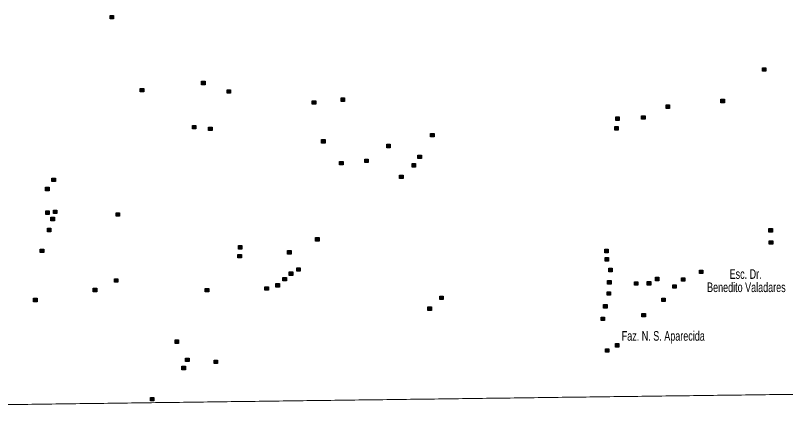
# Model space of a CAD drawing. Extents: x 265.7 to 292.1, y 7676.2 to 7704.2.
# Drawn here: x 279.53 to 285.94, y 7676.18 to 7679.6 of the extents above; entities that cross this region are included whole.
import ezdxf

# ---------------------------------------------------------------- set-up
doc = ezdxf.new("R2010")
doc.units = 0
doc.header["$LTSCALE"] = 0.032
doc.layers.add('2', color=7, linetype='Continuous', lineweight=25)
doc.layers.add('63', color=7, linetype='Continuous', lineweight=13)
doc.layers.add('61', color=7, linetype='Continuous')

msp = doc.modelspace()

# ---------------------------------------------------------------- hatches: boundary and pattern name
at = {"layer": '2'}
for points in [[(280.3175, 7679.5959), (280.3465, 7679.5959), (280.3465, 7679.5669), (280.3175, 7679.5669)], [(285.7441, 7679.1601), (285.7731, 7679.1601), (285.7731, 7679.1311), (285.7441, 7679.1311)], [(281.0785, 7679.0487), (281.1075, 7679.0487), (281.1075, 7679.0197), (281.0785, 7679.0197)], [(280.5692, 7678.9889), (280.5982, 7678.9889), (280.5982, 7678.9599), (280.5692, 7678.9599)], [(281.2916, 7678.9777), (281.3206, 7678.9777), (281.3206, 7678.9487), (281.2916, 7678.9487)], [(282.0001, 7678.8864), (282.0291, 7678.8864), (282.0291, 7678.8574), (282.0001, 7678.8574)], [(282.2391, 7678.9099), (282.2681, 7678.9099), (282.2681, 7678.8809), (282.2391, 7678.8809)], [(285.3995, 7678.8985), (285.4285, 7678.8985), (285.4285, 7678.8695), (285.3995, 7678.8695)], [(284.9427, 7678.8518), (284.9717, 7678.8518), (284.9717, 7678.8228), (284.9427, 7678.8228)], [(284.5247, 7678.7517), (284.5537, 7678.7517), (284.5537, 7678.7227), (284.5247, 7678.7227)], [(284.7393, 7678.7614), (284.7683, 7678.7614), (284.7683, 7678.7324), (284.7393, 7678.7324)], [(281.0027, 7678.6807), (281.0317, 7678.6807), (281.0317, 7678.6517), (281.0027, 7678.6517)], [(281.1367, 7678.6677), (281.1657, 7678.6677), (281.1657, 7678.6387), (281.1367, 7678.6387)], [(284.5158, 7678.671), (284.5448, 7678.671), (284.5448, 7678.642), (284.5158, 7678.642)], [(282.0776, 7678.5637), (282.1066, 7678.5637), (282.1066, 7678.5347), (282.0776, 7678.5347)], [(282.984, 7678.6145), (283.013, 7678.6145), (283.013, 7678.5855), (282.984, 7678.5855)], [(282.6201, 7678.5241), (282.6491, 7678.5241), (282.6491, 7678.4951), (282.6201, 7678.4951)], [(282.8791, 7678.4337), (282.9081, 7678.4337), (282.9081, 7678.4047), (282.8791, 7678.4047)], [(282.227, 7678.382), (282.256, 7678.382), (282.256, 7678.353), (282.227, 7678.353)], [(282.4367, 7678.4006), (282.4657, 7678.4006), (282.4657, 7678.3716), (282.4367, 7678.3716)], [(282.8299, 7678.3636), (282.8589, 7678.3636), (282.8589, 7678.3346), (282.8299, 7678.3346)], [(279.8341, 7678.2432), (279.8631, 7678.2432), (279.8631, 7678.2142), (279.8341, 7678.2142)], [(282.7258, 7678.2683), (282.7548, 7678.2683), (282.7548, 7678.2393), (282.7258, 7678.2393)], [(279.7816, 7678.1673), (279.8106, 7678.1673), (279.8106, 7678.1383), (279.7816, 7678.1383)], [(279.7824, 7677.9705), (279.8114, 7677.9705), (279.8114, 7677.9415), (279.7824, 7677.9415)], [(279.8252, 7677.9171), (279.8542, 7677.9171), (279.8542, 7677.8881), (279.8252, 7677.8881)], [(279.8462, 7677.9769), (279.8752, 7677.9769), (279.8752, 7677.9479), (279.8462, 7677.9479)], [(280.3676, 7677.9552), (280.3966, 7677.9552), (280.3966, 7677.9262), (280.3676, 7677.9262)], [(279.7962, 7677.8261), (279.8252, 7677.8261), (279.8252, 7677.7971), (279.7962, 7677.7971)], [(285.7982, 7677.8236), (285.8272, 7677.8236), (285.8272, 7677.7946), (285.7982, 7677.7946)], [(282.0276, 7677.7477), (282.0566, 7677.7477), (282.0566, 7677.7187), (282.0276, 7677.7187)], [(285.8014, 7677.7219), (285.8304, 7677.7219), (285.8304, 7677.6929), (285.8014, 7677.6929)], [(281.386, 7677.6815), (281.415, 7677.6815), (281.415, 7677.6525), (281.386, 7677.6525)], [(279.7373, 7677.6525), (279.7663, 7677.6525), (279.7663, 7677.6235), (279.7373, 7677.6235)], [(281.3811, 7677.6088), (281.4101, 7677.6088), (281.4101, 7677.5798), (281.3811, 7677.5798)], [(281.7945, 7677.6396), (281.8235, 7677.6396), (281.8235, 7677.6106), (281.7945, 7677.6106)], [(284.4326, 7677.6518), (284.4616, 7677.6518), (284.4616, 7677.6228), (284.4326, 7677.6228)], [(284.4359, 7677.5815), (284.4649, 7677.5815), (284.4649, 7677.5525), (284.4359, 7677.5525)], [(281.8702, 7677.4976), (281.8992, 7677.4976), (281.8992, 7677.4686), (281.8702, 7677.4686)], [(284.4658, 7677.4927), (284.4948, 7677.4927), (284.4948, 7677.4637), (284.4658, 7677.4637)], [(285.2203, 7677.4782), (285.2493, 7677.4782), (285.2493, 7677.4492), (285.2203, 7677.4492)], [(280.3547, 7677.4063), (280.3837, 7677.4063), (280.3837, 7677.3773), (280.3547, 7677.3773)], [(281.7562, 7677.4163), (281.7852, 7677.4163), (281.7852, 7677.3873), (281.7562, 7677.3873)], [(281.8082, 7677.4629), (281.8372, 7677.4629), (281.8372, 7677.4339), (281.8082, 7677.4339)], [(284.8548, 7677.4184), (284.8838, 7677.4184), (284.8838, 7677.3894), (284.8548, 7677.3894)], [(285.071, 7677.4136), (285.1, 7677.4136), (285.1, 7677.3846), (285.071, 7677.3846)], [(281.6056, 7677.3386), (281.6346, 7677.3386), (281.6346, 7677.3096), (281.6056, 7677.3096)], [(281.6968, 7677.3652), (281.7258, 7677.3652), (281.7258, 7677.3362), (281.6968, 7677.3362)], [(284.456, 7677.3909), (284.485, 7677.3909), (284.485, 7677.3619), (284.456, 7677.3619)], [(284.6804, 7677.3812), (284.7094, 7677.3812), (284.7094, 7677.3522), (284.6804, 7677.3522)], [(284.7868, 7677.3829), (284.8158, 7677.3829), (284.8158, 7677.3539), (284.7868, 7677.3539)], [(284.9992, 7677.3555), (285.0282, 7677.3555), (285.0282, 7677.3265), (284.9992, 7677.3265)], [(280.1779, 7677.3264), (280.2069, 7677.3264), (280.2069, 7677.2974), (280.1779, 7677.2974)], [(281.1093, 7677.3256), (281.1383, 7677.3256), (281.1383, 7677.2966), (281.1093, 7677.2966)], [(284.452, 7677.2973), (284.481, 7677.2973), (284.481, 7677.2683), (284.452, 7677.2683)], [(279.6816, 7677.2434), (279.7106, 7677.2434), (279.7106, 7677.2144), (279.6816, 7677.2144)], [(283.0607, 7677.2619), (283.0897, 7677.2619), (283.0897, 7677.2329), (283.0607, 7677.2329)], [(284.9064, 7677.2449), (284.9354, 7677.2449), (284.9354, 7677.2159), (284.9064, 7677.2159)], [(282.9615, 7677.1715), (282.9905, 7677.1715), (282.9905, 7677.1425), (282.9615, 7677.1425)], [(284.423, 7677.1908), (284.452, 7677.1908), (284.452, 7677.1618), (284.423, 7677.1618)], [(284.402, 7677.0867), (284.431, 7677.0867), (284.431, 7677.0577), (284.402, 7677.0577)], [(284.7425, 7677.1182), (284.7715, 7677.1182), (284.7715, 7677.0892), (284.7425, 7677.0892)], [(280.8581, 7676.8971), (280.8871, 7676.8971), (280.8871, 7676.8681), (280.8581, 7676.8681)], [(284.5223, 7676.8665), (284.5513, 7676.8665), (284.5513, 7676.8375), (284.5223, 7676.8375)], [(284.4384, 7676.8244), (284.4674, 7676.8244), (284.4674, 7676.7954), (284.4384, 7676.7954)], [(280.9454, 7676.7454), (280.9744, 7676.7454), (280.9744, 7676.7164), (280.9454, 7676.7164)], [(281.1834, 7676.7293), (281.2124, 7676.7293), (281.2124, 7676.7003), (281.1834, 7676.7003)], [(280.9155, 7676.6776), (280.9445, 7676.6776), (280.9445, 7676.6486), (280.9155, 7676.6486)], [(280.654, 7676.4186), (280.683, 7676.4186), (280.683, 7676.3896), (280.654, 7676.3896)]]:
    msp.add_hatch(color=256, dxfattribs=at).paths.add_polyline_path(points)

# ---------------------------------------------------------------- linework, layer by layer
for points in [[(280.3175, 7679.5959), (280.3465, 7679.5959), (280.3465, 7679.5669), (280.3175, 7679.5669)], [(285.7441, 7679.1601), (285.7731, 7679.1601), (285.7731, 7679.1311), (285.7441, 7679.1311)], [(281.0785, 7679.0487), (281.1075, 7679.0487), (281.1075, 7679.0197), (281.0785, 7679.0197)], [(280.5692, 7678.9889), (280.5982, 7678.9889), (280.5982, 7678.9599), (280.5692, 7678.9599)], [(281.2916, 7678.9777), (281.3206, 7678.9777), (281.3206, 7678.9487), (281.2916, 7678.9487)], [(282.0001, 7678.8864), (282.0291, 7678.8864), (282.0291, 7678.8574), (282.0001, 7678.8574)], [(282.2391, 7678.9099), (282.2681, 7678.9099), (282.2681, 7678.8809), (282.2391, 7678.8809)], [(285.3995, 7678.8985), (285.4285, 7678.8985), (285.4285, 7678.8695), (285.3995, 7678.8695)], [(284.9427, 7678.8518), (284.9717, 7678.8518), (284.9717, 7678.8228), (284.9427, 7678.8228)], [(284.5247, 7678.7517), (284.5537, 7678.7517), (284.5537, 7678.7227), (284.5247, 7678.7227)], [(284.7393, 7678.7614), (284.7683, 7678.7614), (284.7683, 7678.7324), (284.7393, 7678.7324)], [(281.0027, 7678.6807), (281.0317, 7678.6807), (281.0317, 7678.6517), (281.0027, 7678.6517)], [(281.1367, 7678.6677), (281.1657, 7678.6677), (281.1657, 7678.6387), (281.1367, 7678.6387)], [(284.5158, 7678.671), (284.5448, 7678.671), (284.5448, 7678.642), (284.5158, 7678.642)], [(282.0776, 7678.5637), (282.1066, 7678.5637), (282.1066, 7678.5347), (282.0776, 7678.5347)], [(282.984, 7678.6145), (283.013, 7678.6145), (283.013, 7678.5855), (282.984, 7678.5855)], [(282.6201, 7678.5241), (282.6491, 7678.5241), (282.6491, 7678.4951), (282.6201, 7678.4951)], [(282.8791, 7678.4337), (282.9081, 7678.4337), (282.9081, 7678.4047), (282.8791, 7678.4047)], [(282.227, 7678.382), (282.256, 7678.382), (282.256, 7678.353), (282.227, 7678.353)], [(282.4367, 7678.4006), (282.4657, 7678.4006), (282.4657, 7678.3716), (282.4367, 7678.3716)], [(282.8299, 7678.3636), (282.8589, 7678.3636), (282.8589, 7678.3346), (282.8299, 7678.3346)], [(279.8341, 7678.2432), (279.8631, 7678.2432), (279.8631, 7678.2142), (279.8341, 7678.2142)], [(282.7258, 7678.2683), (282.7548, 7678.2683), (282.7548, 7678.2393), (282.7258, 7678.2393)], [(279.7816, 7678.1673), (279.8106, 7678.1673), (279.8106, 7678.1383), (279.7816, 7678.1383)], [(279.7824, 7677.9705), (279.8114, 7677.9705), (279.8114, 7677.9415), (279.7824, 7677.9415)], [(279.8252, 7677.9171), (279.8542, 7677.9171), (279.8542, 7677.8881), (279.8252, 7677.8881)], [(279.8462, 7677.9769), (279.8752, 7677.9769), (279.8752, 7677.9479), (279.8462, 7677.9479)], [(280.3676, 7677.9552), (280.3966, 7677.9552), (280.3966, 7677.9262), (280.3676, 7677.9262)], [(279.7962, 7677.8261), (279.8252, 7677.8261), (279.8252, 7677.7971), (279.7962, 7677.7971)], [(285.7982, 7677.8236), (285.8272, 7677.8236), (285.8272, 7677.7946), (285.7982, 7677.7946)], [(282.0276, 7677.7477), (282.0566, 7677.7477), (282.0566, 7677.7187), (282.0276, 7677.7187)], [(285.8014, 7677.7219), (285.8304, 7677.7219), (285.8304, 7677.6929), (285.8014, 7677.6929)], [(281.386, 7677.6815), (281.415, 7677.6815), (281.415, 7677.6525), (281.386, 7677.6525)], [(279.7373, 7677.6525), (279.7663, 7677.6525), (279.7663, 7677.6235), (279.7373, 7677.6235)], [(281.3811, 7677.6088), (281.4101, 7677.6088), (281.4101, 7677.5798), (281.3811, 7677.5798)], [(281.7945, 7677.6396), (281.8235, 7677.6396), (281.8235, 7677.6106), (281.7945, 7677.6106)], [(284.4326, 7677.6518), (284.4616, 7677.6518), (284.4616, 7677.6228), (284.4326, 7677.6228)], [(284.4359, 7677.5815), (284.4649, 7677.5815), (284.4649, 7677.5525), (284.4359, 7677.5525)], [(281.8702, 7677.4976), (281.8992, 7677.4976), (281.8992, 7677.4686), (281.8702, 7677.4686)], [(284.4658, 7677.4927), (284.4948, 7677.4927), (284.4948, 7677.4637), (284.4658, 7677.4637)], [(285.2203, 7677.4782), (285.2493, 7677.4782), (285.2493, 7677.4492), (285.2203, 7677.4492)], [(280.3547, 7677.4063), (280.3837, 7677.4063), (280.3837, 7677.3773), (280.3547, 7677.3773)], [(281.7562, 7677.4163), (281.7852, 7677.4163), (281.7852, 7677.3873), (281.7562, 7677.3873)], [(281.8082, 7677.4629), (281.8372, 7677.4629), (281.8372, 7677.4339), (281.8082, 7677.4339)], [(284.8548, 7677.4184), (284.8838, 7677.4184), (284.8838, 7677.3894), (284.8548, 7677.3894)], [(285.071, 7677.4136), (285.1, 7677.4136), (285.1, 7677.3846), (285.071, 7677.3846)], [(281.6056, 7677.3386), (281.6346, 7677.3386), (281.6346, 7677.3096), (281.6056, 7677.3096)], [(281.6968, 7677.3652), (281.7258, 7677.3652), (281.7258, 7677.3362), (281.6968, 7677.3362)], [(284.456, 7677.3909), (284.485, 7677.3909), (284.485, 7677.3619), (284.456, 7677.3619)], [(284.6804, 7677.3812), (284.7094, 7677.3812), (284.7094, 7677.3522), (284.6804, 7677.3522)], [(284.7868, 7677.3829), (284.8158, 7677.3829), (284.8158, 7677.3539), (284.7868, 7677.3539)], [(284.9992, 7677.3555), (285.0282, 7677.3555), (285.0282, 7677.3265), (284.9992, 7677.3265)], [(280.1779, 7677.3264), (280.2069, 7677.3264), (280.2069, 7677.2974), (280.1779, 7677.2974)], [(281.1093, 7677.3256), (281.1383, 7677.3256), (281.1383, 7677.2966), (281.1093, 7677.2966)], [(284.452, 7677.2973), (284.481, 7677.2973), (284.481, 7677.2683), (284.452, 7677.2683)], [(279.6816, 7677.2434), (279.7106, 7677.2434), (279.7106, 7677.2144), (279.6816, 7677.2144)], [(283.0607, 7677.2619), (283.0897, 7677.2619), (283.0897, 7677.2329), (283.0607, 7677.2329)], [(284.9064, 7677.2449), (284.9354, 7677.2449), (284.9354, 7677.2159), (284.9064, 7677.2159)], [(282.9615, 7677.1715), (282.9905, 7677.1715), (282.9905, 7677.1425), (282.9615, 7677.1425)], [(284.423, 7677.1908), (284.452, 7677.1908), (284.452, 7677.1618), (284.423, 7677.1618)], [(284.402, 7677.0867), (284.431, 7677.0867), (284.431, 7677.0577), (284.402, 7677.0577)], [(284.7425, 7677.1182), (284.7715, 7677.1182), (284.7715, 7677.0892), (284.7425, 7677.0892)], [(280.8581, 7676.8971), (280.8871, 7676.8971), (280.8871, 7676.8681), (280.8581, 7676.8681)], [(284.5223, 7676.8665), (284.5513, 7676.8665), (284.5513, 7676.8375), (284.5223, 7676.8375)], [(284.4384, 7676.8244), (284.4674, 7676.8244), (284.4674, 7676.7954), (284.4384, 7676.7954)], [(280.9454, 7676.7454), (280.9744, 7676.7454), (280.9744, 7676.7164), (280.9454, 7676.7164)], [(281.1834, 7676.7293), (281.2124, 7676.7293), (281.2124, 7676.7003), (281.1834, 7676.7003)], [(280.9155, 7676.6776), (280.9445, 7676.6776), (280.9445, 7676.6486), (280.9155, 7676.6486)], [(280.654, 7676.4186), (280.683, 7676.4186), (280.683, 7676.3896), (280.654, 7676.3896)]]:
    msp.add_lwpolyline(points, close=True, dxfattribs=at)
at = {"layer": '63'}
msp.add_spline([(266.1055, 7676.1764), (266.6361, 7676.1838), (267.1667, 7676.1913), (267.6972, 7676.1987), (268.2278, 7676.2061), (268.7584, 7676.2135), (269.2889, 7676.2209), (269.8195, 7676.2283), (270.3501, 7676.2356), (270.8806, 7676.2429), (271.4112, 7676.2502), (271.9418, 7676.2575), (272.4723, 7676.2648), (273.0029, 7676.2721), (273.5335, 7676.2793), (274.064, 7676.2865), (274.5946, 7676.2937), (275.1251, 7676.3009), (275.6557, 7676.3081), (276.1862, 7676.3153), (276.7168, 7676.3224), (277.2473, 7676.3295), (277.7779, 7676.3366), (278.3084, 7676.3437), (278.839, 7676.3508), (279.3695, 7676.3578), (279.9, 7676.3649), (280.4306, 7676.3719), (280.9611, 7676.3789), (281.4917, 7676.3859), (282.0222, 7676.3929), (282.5527, 7676.3998), (283.0833, 7676.4067), (283.6138, 7676.4137), (284.1443, 7676.4206), (284.6749, 7676.4275), (285.2054, 7676.4343), (285.7359, 7676.4412), (286.2665, 7676.448), (286.797, 7676.4548), (287.3275, 7676.4616), (287.858, 7676.4684), (288.3886, 7676.4752), (288.9191, 7676.4819), (289.4496, 7676.4887), (289.9801, 7676.4954), (290.5106, 7676.5021), (291.0411, 7676.5087), (291.5717, 7676.5154), (292.1022, 7676.5221)], degree=3, dxfattribs=at)

# ---------------------------------------------------------------- texts
at = {"layer": '61', "width": 0.7}
for s, p in [('         Esc. Dr.', (285.2841, 7677.4051)), ('Benedito Valadares', (285.2841, 7677.2951)), ('Faz. N. S. Aparecida', (284.5741, 7676.8905))]:
    msp.add_text(s, height=0.08, dxfattribs=at).set_placement(p)

doc.saveas('drawing.dxf')
